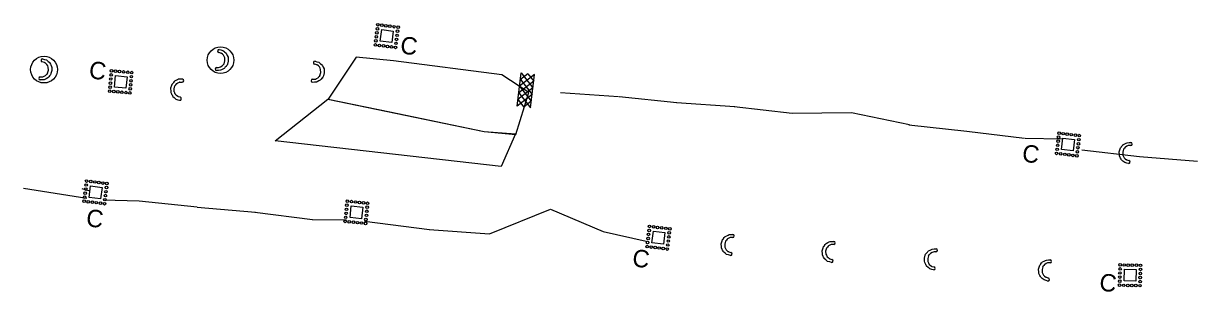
# Model space of a CAD drawing. Extents: x 2470000 to 2520000, y 340000 to 380000.
# Drawn here: x 2480859 to 2481867, y 366051 to 366283 of the extents above; entities that cross this region are included whole.
import ezdxf

# ---------------------------------------------------------------- set-up
doc = ezdxf.new("R2010")
doc.units = 0
for name, color, linetype in [('Bare Soil (Coastal) Drainage Area Border FG Drainage', 7, 'Continuous'), ('Coir Fiber Wattle with PAM Both CELL', 7, 'Continuous'), ('Coir Fiber Wattle with PAM CG CELL', 7, 'Continuous'), ('Label C CG CELL', 7, 'Continuous'), ('Prop Guardrail Anchor Unit CELL', 7, 'Continuous'), ('Prop Structure Anchor Unit CELL', 7, 'Continuous'), ('Rock Inlet Sediment Trap Type C CG CELL', 7, 'Continuous'), ('Rock Silt Check Type A Both CELL', 7, 'Continuous'), ('Scratch_Level_5', 7, 'Continuous'), ('Sheet Data Field CELL', 7, 'Continuous'), ('Wattle Both CELL', 7, 'Continuous'), ('Wattle CG CELL', 7, 'Continuous')]:
    doc.layers.add(name, color=color, linetype=linetype)

# ---------------------------------------------------------------- blocks, each defined once
blk = doc.blocks.new('C2')
at = {"layer": 'Prop Guardrail Anchor Unit CELL'}
blk.add_text('C', height=0.3, dxfattribs=at).set_placement((-0.161, -0.136))
blk = doc.blocks.new('C1')
at = {"layer": 'Label C CG CELL'}
blk.add_text('C', height=0.3, dxfattribs=at).set_placement((-0.161, -0.136))

msp = doc.modelspace()

# ---------------------------------------------------------------- linework, layer by layer
at = {"layer": 'Bare Soil (Coastal) Drainage Area Border FG Drainage'}
for points in [[(2481144.5, 366253.7), (2481120.5, 366217.8), (2481173.6, 366206.7), (2481254.6, 366189.8), (2481281.6, 366187.4), (2481292.9, 366223.5), (2481269.6, 366238.6), (2481176.7, 366250.7)], [(2481281.4, 366187.9), (2481269.1, 366159.6), (2481074.9, 366181.9), (2481120.2, 366217.8), (2481254.6, 366189.8)]]:
    msp.add_lwpolyline(points, close=True, dxfattribs=at)
at = {"layer": 'Coir Fiber Wattle with PAM Both CELL'}
for p, q in [((2481028.4, 366257.3), (2481026.6, 366257.9)), ((2481028.4, 366257.3), (2481028.7, 366257.2)), ((2481029.8, 366256.3), (2481028.7, 366257.2)), ((2481030.6, 366255.6), (2481029.8, 366256.3)), ((2481028.2, 366245.5), (2481029.5, 366246.2)), ((2481029.6, 366246.4), (2481029.5, 366246.2)), ((2481029.6, 366246.4), (2481030.3, 366247.2)), ((2481031.1, 366248.2), (2481030.3, 366247.2)), ((2481031.2, 366254.3), (2481030.6, 366255.6)), ((2481031.1, 366248.2), (2481031.8, 366250.7)), ((2481031.7, 366253.2), (2481031.2, 366254.3)), ((2481031.8, 366250.7), (2481031.7, 366253.2)), ((2481031.8, 366250.7), (2481031.8, 366250.7)), ((2481024.8, 366244.9), (2481026.4, 366245)), ((2481026.4, 366245), (2481027.2, 366245.1)), ((2481027.2, 366245.1), (2481028.2, 366245.5))]:
    msp.add_line(p, q, dxfattribs=at)
msp.add_lwpolyline([(2481026.9, 366260.5), (2481028.4, 366260), (2481030.1, 366259.5), (2481030.8, 366259), (2481031.6, 366258.3), (2481032.9, 366257.2), (2481033, 366257.1), (2481033.2, 366256.8), (2481033.2, 366256.7), (2481033.6, 366255.8), (2481033.9, 366255.2), (2481034.6, 366253.9), (2481034.6, 366252.9), (2481034.8, 366250.3), (2481034.8, 366250.3), (2481034, 366247.8), (2481033.7, 366246.8), (2481032.9, 366246), (2481032.8, 366245.8), (2481032.2, 366245.1), (2481031.7, 366244.5), (2481031.6, 366244.4), (2481031.3, 366244.1), (2481031.3, 366244.1), (2481030, 366243.4), (2481028.8, 366242.8), (2481028, 366242.5), (2481026.3, 366242.4), (2481024.7, 366242.3)], dxfattribs=at)
msp.add_circle((2481028.1, 366251.2), 11.5, dxfattribs=at)
for centre, radius, start in [((2481026.8, 366259.2), 1.3, 83.0023), ((2481024.9, 366243.6), 1.33, 91.8897)]:
    msp.add_arc(centre, radius, start, 263.0023, dxfattribs=at)
at = {"layer": 'Coir Fiber Wattle with PAM CG CELL'}
for p, q in [((2480876.8, 366249.2), (2480875, 366249.8)), ((2480876.8, 366249.2), (2480877.1, 366249.1)), ((2480878.3, 366248.2), (2480877.1, 366249.1)), ((2480879, 366247.5), (2480878.3, 366248.2)), ((2480879.7, 366246.2), (2480879, 366247.5)), ((2480880.2, 366245.1), (2480879.7, 366246.2)), ((2480873.3, 366236.8), (2480874.8, 366236.9)), ((2480874.8, 366236.9), (2480875.6, 366237)), ((2480875.6, 366237), (2480876.6, 366237.4)), ((2480876.6, 366237.4), (2480877.9, 366238.1)), ((2480878.1, 366238.3), (2480877.9, 366238.1)), ((2480878.1, 366238.3), (2480878.8, 366239.1)), ((2480879.5, 366240.1), (2480878.8, 366239.1)), ((2480879.5, 366240.1), (2480880.3, 366242.6)), ((2480880.3, 366242.6), (2480880.2, 366245.1)), ((2480880.3, 366242.6), (2480880.3, 366242.6))]:
    msp.add_line(p, q, dxfattribs=at)
msp.add_lwpolyline([(2480875.3, 366252.4), (2480876.8, 366251.9), (2480878.6, 366251.4), (2480879.2, 366250.9), (2480880, 366250.2), (2480881.4, 366249.1), (2480881.4, 366249.1), (2480881.6, 366248.7), (2480881.6, 366248.6), (2480882, 366247.7), (2480882.3, 366247.1), (2480883, 366245.8), (2480883.1, 366244.8), (2480883.2, 366242.2), (2480883.2, 366242.2), (2480882.4, 366239.7), (2480882.1, 366238.7), (2480881.4, 366237.9), (2480881.2, 366237.7), (2480880.6, 366237), (2480880.1, 366236.4), (2480880, 366236.3), (2480879.8, 366236), (2480879.8, 366236), (2480878.4, 366235.3), (2480877.2, 366234.7), (2480876.5, 366234.4), (2480874.7, 366234.3), (2480873.2, 366234.2)], dxfattribs=at)
msp.add_circle((2480876.5, 366243.1), 11.5, dxfattribs=at)
for centre, radius, start in [((2480875.2, 366251.1), 1.3, 83.0023), ((2480873.3, 366235.5), 1.33, 91.8897)]:
    msp.add_arc(centre, radius, start, 263.0023, dxfattribs=at)
at = {"layer": 'Prop Structure Anchor Unit CELL'}
for points in [[(2481166.5, 366277.5), (2481176.4, 366276.3), (2481175.2, 366266.4), (2481165.2, 366267.6)], [(2481751.6, 366184.2), (2481761.6, 366183), (2481760.3, 366173.1), (2481750.4, 366174.3)], [(2480916.4, 366143), (2480926.3, 366141.8), (2480925.1, 366131.9), (2480915.2, 366133.1)], [(2481140.4, 366125.8), (2481150.3, 366124.8), (2481149.3, 366114.8), (2481139.4, 366115.8)], [(2481399.9, 366104), (2481409.8, 366102.8), (2481408.6, 366092.9), (2481398.6, 366094.1)], [(2481804.2, 366061.3), (2481804.4, 366071.3), (2481814.4, 366071), (2481814.2, 366061)]]:
    msp.add_lwpolyline(points, close=True, dxfattribs=at)
for centre in [(2481162.8, 366278.2), (2481163.2, 366281.7), (2481166.7, 366281.3), (2481170.1, 366280.8), (2481173.6, 366280.4), (2481177.1, 366280), (2481180.1, 366276.1), (2481180.6, 366279.6), (2481161.5, 366267.8), (2481161.9, 366271.3), (2481162.3, 366274.7), (2481178.8, 366265.7), (2481179.3, 366269.1), (2481179.7, 366272.6), (2481161.1, 366264.3), (2481164.5, 366263.9), (2481168, 366263.5), (2481171.5, 366263), (2481174.9, 366262.6), (2481178.4, 366262.2), (2481747.9, 366184.9), (2481748.4, 366188.4), (2481751.8, 366188), (2481755.3, 366187.6), (2481758.8, 366187.1), (2481762.3, 366186.7), (2481765.7, 366186.3), (2481746.7, 366174.5), (2481747.1, 366178), (2481747.5, 366181.5), (2481764.5, 366175.9), (2481764.9, 366179.3), (2481765.3, 366182.8), (2481746.2, 366171), (2481749.7, 366170.6), (2481753.2, 366170.2), (2481756.7, 366169.8), (2481760.1, 366169.3), (2481763.6, 366168.9), (2481764, 366172.4), (2480913.1, 366147.2), (2480916.6, 366146.8), (2480920.1, 366146.4), (2480923.6, 366146), (2480927, 366145.5), (2480930.5, 366145.1), (2480911.9, 366136.8), (2480912.3, 366140.3), (2480912.7, 366143.8), (2480929.2, 366134.7), (2480929.7, 366138.1), (2480930.1, 366141.6), (2480911, 366129.9), (2480911.4, 366133.3), (2480914.5, 366129.4), (2480918, 366129), (2480921.4, 366128.6), (2480924.9, 366128.2), (2480928.4, 366127.7), (2480928.8, 366131.2), (2481136.6, 366126.4), (2481137, 366129.9), (2481140.5, 366129.5), (2481144, 366129.2), (2481147.4, 366128.8), (2481150.9, 366128.5), (2481154.1, 366124.7), (2481154.4, 366128.1), (2481135.6, 366116), (2481135.9, 366119.4), (2481136.3, 366122.9), (2481153, 366114.2), (2481153.4, 366117.7), (2481153.7, 366121.2), (2481135.2, 366112.5), (2481138.7, 366112.1), (2481142.2, 366111.8), (2481145.7, 366111.4), (2481149.2, 366111.1), (2481152.7, 366110.7), (2481396.2, 366104.7), (2481396.6, 366108.2), (2481400.1, 366107.8), (2481403.5, 366107.3), (2481407, 366106.9), (2481410.5, 366106.5), (2481414, 366106.1), (2481394.9, 366094.3), (2481395.3, 366097.8), (2481395.7, 366101.3), (2481412.7, 366095.6), (2481413.1, 366099.1), (2481413.5, 366102.6), (2481394.5, 366090.8), (2481397.9, 366090.4), (2481401.4, 366090), (2481404.9, 366089.6), (2481408.3, 366089.1), (2481411.8, 366088.7), (2481412.2, 366092.2), (2481800.8, 366075.1), (2481804.3, 366075), (2481807.7, 366074.9), (2481811.2, 366074.9), (2481814.7, 366074.8), (2481818.2, 366074.7), (2481800.5, 366064.6), (2481800.7, 366071.6), (2481800.6, 366068.1), (2481818, 366064.2), (2481818.2, 366071.2), (2481818.1, 366067.7), (2481800.3, 366057.6), (2481800.4, 366061.1), (2481803.8, 366057.5), (2481807.3, 366057.4), (2481810.8, 366057.4), (2481814.3, 366057.3), (2481817.8, 366057.2), (2481817.9, 366060.7)]:
    msp.add_circle(centre, 1.12, dxfattribs=at)
at = {"layer": 'Rock Inlet Sediment Trap Type C CG CELL'}
msp.add_lwpolyline([(2480937.8, 366237.9), (2480947.8, 366237), (2480946.9, 366227.1), (2480937, 366227.9)], close=True, dxfattribs=at)
for centre in [(2480933.8, 366235), (2480934.1, 366238.5), (2480934.4, 366242), (2480937.9, 366241.7), (2480941.4, 366241.4), (2480944.9, 366241.1), (2480948.4, 366240.8), (2480951.5, 366237), (2480951.8, 366240.5), (2480933.2, 366228), (2480933.5, 366231.5), (2480950.6, 366226.5), (2480950.9, 366230), (2480951.2, 366233.5), (2480932.9, 366224.5), (2480936.4, 366224.2), (2480939.9, 366223.9), (2480943.4, 366223.6), (2480946.9, 366223.3), (2480950.3, 366223)]:
    msp.add_circle(centre, 1.12, dxfattribs=at)
at = {"layer": 'Rock Silt Check Type A Both CELL'}
for p, q in [((2481282.8, 366211.6), (2481286.3, 366240.3)), ((2481297.8, 366238.9), (2481284.9, 366228.8)), ((2481292, 366239.6), (2481285.6, 366234.5)), ((2481286.3, 366240.3), (2481296.4, 366227.4)), ((2481292, 366239.6), (2481297.1, 366233.1)), ((2481294.3, 366210.2), (2481297.8, 366238.9)), ((2481296.4, 366227.4), (2481283.5, 366217.3)), ((2481297.1, 366233.1), (2481284.2, 366223.1)), ((2481284.9, 366228.8), (2481295, 366215.9)), ((2481285.6, 366234.5), (2481295.7, 366221.7)), ((2481295.7, 366221.7), (2481282.8, 366211.6)), ((2481283.6, 366217.2), (2481288.5, 366210.9)), ((2481284.2, 366223.1), (2481294.3, 366210.2)), ((2481295, 366215.9), (2481288.5, 366210.9))]:
    msp.add_line(p, q, dxfattribs=at)
at = {"layer": 'Sheet Data Field CELL'}
for p, q in [((2481370, 366219.7), (2481320.1, 366223)), ((2481420.1, 366214.6), (2481370.4, 366219.6)), ((2481469.7, 366211.2), (2481419.8, 366214.6)), ((2481519.2, 366205.3), (2481469.2, 366211.2)), ((2481570.1, 366205.8), (2481519.2, 366205.3)), ((2481619.8, 366195.5), (2481570.1, 366205.8)), ((2481619.3, 366195.5), (2481669, 366190)), ((2481669, 366190), (2481718.7, 366184)), ((2481719.1, 366184), (2481751.1, 366183.5)), ((2481767.9, 366174.1), (2481817.5, 366168.2)), ((2481817.4, 366168.2), (2481867.2, 366164.2)), ((2480858.9, 366141.2), (2480913.3, 366132.4)), ((2480927.3, 366131.1), (2480958.2, 366130.3)), ((2480958.2, 366130.3), (2481007.9, 366124.9)), ((2481008.1, 366124.8), (2481058, 366120.5)), ((2481057.5, 366120.5), (2481107.1, 366114)), ((2481259.2, 366101.8), (2481311.4, 366123.1)), ((2481311.4, 366123.1), (2481356.7, 366103.8)), ((2481107.3, 366113.9), (2481136.1, 366114.1)), ((2481151.7, 366112.8), (2481207.5, 366105.6)), ((2481207.4, 366105.6), (2481259.2, 366101.8)), ((2481356.7, 366103.8), (2481393.8, 366095.6))]:
    msp.add_line(p, q, dxfattribs=at)
msp.add_lwpolyline([(2480909.1, 366140.9), (2480915.9, 366138.7)], dxfattribs=at)
at = {"layer": 'Wattle Both CELL'}
for p, q in [((2481110.8, 366247.2), (2481109, 366247.8)), ((2481110.8, 366247.2), (2481111.1, 366247.1)), ((2481112.2, 366246.2), (2481111.1, 366247.1)), ((2481113, 366245.5), (2481112.2, 366246.2)), ((2481110.6, 366235.4), (2481111.9, 366236.1)), ((2481112, 366236.2), (2481111.9, 366236.1)), ((2481112, 366236.2), (2481112.7, 366237.1)), ((2481113.5, 366238), (2481112.7, 366237.1)), ((2481113.6, 366244.2), (2481113, 366245.5)), ((2481113.5, 366238), (2481114.2, 366240.6)), ((2481114.1, 366243.1), (2481113.6, 366244.2)), ((2481114.2, 366240.6), (2481114.1, 366243.1)), ((2481114.2, 366240.6), (2481114.2, 366240.6)), ((2481107.2, 366234.8), (2481108.8, 366234.9)), ((2481108.8, 366234.9), (2481109.6, 366234.9)), ((2481109.6, 366234.9), (2481110.6, 366235.4)), ((2481803.7, 366174.5), (2481804.5, 366175.5)), ((2481805.2, 366176.3), (2481804.5, 366175.5)), ((2481805.2, 366176.3), (2481805.3, 366176.5)), ((2481806.6, 366177.2), (2481805.3, 366176.5)), ((2481807.6, 366177.7), (2481806.6, 366177.2)), ((2481808.4, 366177.7), (2481807.6, 366177.7)), ((2481809.9, 366177.8), (2481808.4, 366177.7)), ((2481803.7, 366174.5), (2481803, 366172)), ((2481803, 366172), (2481803, 366172)), ((2481803, 366172), (2481803.1, 366169.5)), ((2481803.1, 366169.5), (2481803.6, 366168.4)), ((2481803.6, 366168.4), (2481804.2, 366167.1)), ((2481804.2, 366167.1), (2481805, 366166.4)), ((2481805, 366166.4), (2481806.1, 366165.5)), ((2481806.4, 366165.4), (2481806.1, 366165.5)), ((2481806.4, 366165.4), (2481808.2, 366164.8)), ((2481461.9, 366095.4), (2481461.1, 366092.9)), ((2481461.9, 366095.4), (2481462.6, 366096.3)), ((2481463.3, 366097.2), (2481462.6, 366096.3)), ((2481463.3, 366097.2), (2481463.5, 366097.4)), ((2481464.8, 366098), (2481463.5, 366097.4)), ((2481465.7, 366098.5), (2481464.8, 366098)), ((2481466.5, 366098.6), (2481465.7, 366098.5)), ((2481468.1, 366098.7), (2481466.5, 366098.6)), ((2481461.1, 366092.9), (2481461.1, 366092.9)), ((2481461.1, 366092.9), (2481461.2, 366090.4)), ((2481461.2, 366090.4), (2481461.7, 366089.3)), ((2481461.7, 366089.3), (2481462.3, 366088)), ((2481462.3, 366088), (2481463.1, 366087.3)), ((2481463.1, 366087.3), (2481464.2, 366086.3)), ((2481464.6, 366086.2), (2481464.2, 366086.3)), ((2481464.6, 366086.2), (2481466.3, 366085.7)), ((2481548.6, 366089.4), (2481547.8, 366086.9)), ((2481547.8, 366086.9), (2481547.8, 366086.9)), ((2481547.8, 366086.9), (2481548, 366084.4)), ((2481548.6, 366089.4), (2481549.4, 366090.4)), ((2481550.1, 366091.2), (2481549.4, 366090.4)), ((2481550.1, 366091.2), (2481550.2, 366091.4)), ((2481551.5, 366092.1), (2481550.2, 366091.4)), ((2481552.5, 366092.6), (2481551.5, 366092.1)), ((2481553.3, 366092.6), (2481552.5, 366092.6)), ((2481554.8, 366092.7), (2481553.3, 366092.6)), ((2481637.8, 366084.8), (2481637.1, 366083.9)), ((2481637.8, 366084.8), (2481637.9, 366085)), ((2481639.2, 366085.6), (2481637.9, 366085)), ((2481640.2, 366086.1), (2481639.2, 366085.6)), ((2481641, 366086.2), (2481640.2, 366086.1)), ((2481642.6, 366086.2), (2481641, 366086.2)), ((2481548, 366084.4), (2481548.5, 366083.3)), ((2481548.5, 366083.3), (2481549.1, 366082)), ((2481549.1, 366082), (2481549.9, 366081.3)), ((2481549.9, 366081.3), (2481551, 366080.4)), ((2481551.3, 366080.3), (2481551, 366080.4)), ((2481551.3, 366080.3), (2481553.1, 366079.7)), ((2481636.3, 366083), (2481635.6, 366080.5)), ((2481635.6, 366080.5), (2481635.6, 366080.5)), ((2481635.6, 366080.5), (2481635.7, 366077.9)), ((2481635.7, 366077.9), (2481636.2, 366076.8)), ((2481636.2, 366076.8), (2481636.8, 366075.5)), ((2481636.3, 366083), (2481637.1, 366083.9)), ((2481636.8, 366075.5), (2481637.6, 366074.9)), ((2481637.6, 366074.9), (2481638.7, 366073.9)), ((2481735.9, 366075.3), (2481735.2, 366074.5)), ((2481735.9, 366075.3), (2481736, 366075.5)), ((2481737.3, 366076.2), (2481736, 366075.5)), ((2481738.3, 366076.7), (2481737.3, 366076.2)), ((2481739.1, 366076.7), (2481738.3, 366076.7)), ((2481740.7, 366076.8), (2481739.1, 366076.7)), ((2481639, 366073.8), (2481638.7, 366073.9)), ((2481639, 366073.8), (2481640.8, 366073.3)), ((2481734.4, 366073.5), (2481733.7, 366071)), ((2481733.7, 366071), (2481733.7, 366071)), ((2481733.7, 366071), (2481733.8, 366068.5)), ((2481733.8, 366068.5), (2481734.3, 366067.4)), ((2481734.3, 366067.4), (2481734.9, 366066.1)), ((2481734.4, 366073.5), (2481735.2, 366074.5)), ((2481734.9, 366066.1), (2481735.7, 366065.4)), ((2481735.7, 366065.4), (2481736.8, 366064.5)), ((2481737.1, 366064.4), (2481736.8, 366064.5)), ((2481737.1, 366064.4), (2481738.9, 366063.8))]:
    msp.add_line(p, q, dxfattribs=at)
for points in [[(2481109.3, 366250.4), (2481110.8, 366249.9), (2481112.5, 366249.4), (2481113.2, 366248.8), (2481114, 366248.2), (2481115.3, 366247.1), (2481115.4, 366247), (2481115.6, 366246.6), (2481115.6, 366246.6), (2481116, 366245.7), (2481116.3, 366245.1), (2481117, 366243.8), (2481117, 366242.7), (2481117.2, 366240.2), (2481117.2, 366240.2), (2481116.4, 366237.7), (2481116.1, 366236.7), (2481115.3, 366235.8), (2481115.2, 366235.7), (2481114.5, 366234.9), (2481114.1, 366234.4), (2481114, 366234.2), (2481113.7, 366234), (2481113.7, 366234), (2481112.4, 366233.3), (2481111.1, 366232.7), (2481110.4, 366232.4), (2481108.7, 366232.2), (2481107.1, 366232.1)], [(2481807.9, 366162.2), (2481806.4, 366162.7), (2481804.7, 366163.2), (2481804, 366163.7), (2481803.2, 366164.4), (2481801.8, 366165.5), (2481801.8, 366165.6), (2481801.6, 366166), (2481801.6, 366166), (2481801.2, 366166.9), (2481800.9, 366167.5), (2481800.2, 366168.8), (2481800.2, 366169.8), (2481800, 366172.4), (2481800, 366172.4), (2481800.8, 366174.9), (2481801.1, 366175.9), (2481801.9, 366176.7), (2481802, 366176.9), (2481802.6, 366177.6), (2481803.1, 366178.2), (2481803.2, 366178.3), (2481803.5, 366178.6), (2481803.5, 366178.6), (2481804.8, 366179.3), (2481806, 366179.9), (2481806.8, 366180.2), (2481808.5, 366180.3), (2481810.1, 366180.4)], [(2481466, 366083.1), (2481464.5, 366083.6), (2481462.8, 366084.1), (2481462.1, 366084.6), (2481461.4, 366085.3), (2481460, 366086.4), (2481460, 366086.4), (2481459.8, 366086.8), (2481459.7, 366086.9), (2481459.3, 366087.8), (2481459, 366088.4), (2481458.4, 366089.7), (2481458.3, 366090.7), (2481458.1, 366093.3), (2481458.1, 366093.3), (2481458.9, 366095.8), (2481459.3, 366096.8), (2481460, 366097.6), (2481460.2, 366097.8), (2481460.8, 366098.5), (2481461.3, 366099.1), (2481461.4, 366099.2), (2481461.6, 366099.5), (2481461.6, 366099.5), (2481463, 366100.2), (2481464.2, 366100.7), (2481464.9, 366101.1), (2481466.7, 366101.2), (2481468.2, 366101.3)], [(2481552.8, 366077.1), (2481551.3, 366077.6), (2481549.5, 366078.1), (2481548.9, 366078.6), (2481548.1, 366079.3), (2481546.7, 366080.4), (2481546.7, 366080.5), (2481546.5, 366080.9), (2481546.5, 366080.9), (2481546.1, 366081.8), (2481545.8, 366082.4), (2481545.1, 366083.7), (2481545.1, 366084.7), (2481544.9, 366087.3), (2481544.9, 366087.3), (2481545.7, 366089.8), (2481546, 366090.8), (2481546.8, 366091.6), (2481546.9, 366091.8), (2481547.5, 366092.6), (2481548, 366093.1), (2481548.1, 366093.2), (2481548.4, 366093.5), (2481548.4, 366093.5), (2481549.7, 366094.2), (2481550.9, 366094.8), (2481551.7, 366095.1), (2481553.4, 366095.2), (2481555, 366095.3)], [(2481640.5, 366070.7), (2481639, 366071.1), (2481637.3, 366071.7), (2481636.6, 366072.2), (2481635.9, 366072.8), (2481634.5, 366074), (2481634.4, 366074), (2481634.3, 366074.4), (2481634.2, 366074.5), (2481633.8, 366075.3), (2481633.5, 366075.9), (2481632.9, 366077.2), (2481632.8, 366078.3), (2481632.6, 366080.8), (2481632.6, 366080.8), (2481633.4, 366083.4), (2481633.7, 366084.3), (2481634.5, 366085.2), (2481634.6, 366085.4), (2481635.3, 366086.1), (2481635.7, 366086.7), (2481635.8, 366086.8), (2481636.1, 366087.1), (2481636.1, 366087.1), (2481637.5, 366087.7), (2481638.7, 366088.3), (2481639.4, 366088.7), (2481641.1, 366088.8), (2481642.7, 366088.9)], [(2481738.6, 366061.2), (2481737.1, 366061.7), (2481735.4, 366062.2), (2481734.7, 366062.7), (2481733.9, 366063.4), (2481732.6, 366064.5), (2481732.5, 366064.6), (2481732.3, 366065), (2481732.3, 366065), (2481731.9, 366065.9), (2481731.6, 366066.5), (2481730.9, 366067.8), (2481730.9, 366068.8), (2481730.7, 366071.4), (2481730.7, 366071.4), (2481731.5, 366073.9), (2481731.8, 366074.9), (2481732.6, 366075.7), (2481732.7, 366075.9), (2481733.3, 366076.7), (2481733.8, 366077.2), (2481733.9, 366077.3), (2481734.2, 366077.6), (2481734.2, 366077.6), (2481735.5, 366078.3), (2481736.7, 366078.9), (2481737.5, 366079.2), (2481739.2, 366079.3), (2481740.8, 366079.5)]]:
    msp.add_lwpolyline(points, dxfattribs=at)
for centre, radius, start, end in [((2481109.1, 366249.1), 1.3, 83.0023, 263.0023), ((2481107.3, 366233.5), 1.33, 91.8897, 263.0023), ((2481809.9, 366179.1), 1.33, 271.8897, 83.0023), ((2481808, 366163.5), 1.3, 263.0023, 83.0023), ((2481468, 366100), 1.33, 271.8897, 83.0023), ((2481554.8, 366094), 1.33, 271.8897, 83.0023), ((2481466.2, 366084.4), 1.3, 263.0023, 83.0023), ((2481642.5, 366087.6), 1.33, 271.8897, 83.0023), ((2481552.9, 366078.4), 1.3, 263.0023, 83.0023), ((2481740.6, 366078.1), 1.33, 271.8897, 83.0023), ((2481640.7, 366072), 1.3, 263.0023, 83.0023), ((2481738.7, 366062.5), 1.3, 263.0023, 83.0023)]:
    msp.add_arc(centre, radius, start, end, dxfattribs=at)
at = {"layer": 'Wattle CG CELL'}
for p, q in [((2480988.2, 366226.6), (2480988.9, 366229.1)), ((2480988.2, 366226.6), (2480988.2, 366226.6)), ((2480988.3, 366224), (2480988.2, 366226.6)), ((2480988.9, 366229.1), (2480989.7, 366230)), ((2480989.7, 366230), (2480990.6, 366231.1)), ((2480990.6, 366231.1), (2480991.5, 366231.6)), ((2480991.5, 366231.6), (2480992.8, 366232.2)), ((2480993.2, 366232.2), (2480992.8, 366232.2)), ((2480993.2, 366232.2), (2480995, 366232.3)), ((2480988.3, 366224), (2480988.8, 366222.9)), ((2480989.2, 366221.9), (2480988.8, 366222.9)), ((2480989.2, 366221.9), (2480989.3, 366221.7)), ((2480990.4, 366220.7), (2480989.3, 366221.7)), ((2480991.3, 366220), (2480990.4, 366220.7)), ((2480992, 366219.8), (2480991.3, 366220)), ((2480993.5, 366219.3), (2480992, 366219.8))]:
    msp.add_line(p, q, dxfattribs=at)
msp.add_lwpolyline([(2480995.4, 366234.9), (2480993.8, 366234.8), (2480992, 366234.8), (2480991.2, 366234.4), (2480990.3, 366234), (2480988.7, 366233.2), (2480988.7, 366233.2), (2480988.4, 366232.8), (2480988.3, 366232.8), (2480987.7, 366232.1), (2480987.3, 366231.5), (2480986.3, 366230.4), (2480986, 366229.4), (2480985.2, 366227), (2480985.2, 366227), (2480985.4, 366224.4), (2480985.4, 366223.3), (2480985.9, 366222.3), (2480986, 366222.1), (2480986.5, 366221.3), (2480986.8, 366220.6), (2480986.9, 366220.4), (2480987, 366220.1), (2480987, 366220.1), (2480988.2, 366219.1), (2480989.2, 366218.3), (2480989.8, 366217.8), (2480991.5, 366217.2), (2480993, 366216.7)], dxfattribs=at)
for centre, radius, end in [((2480995.2, 366233.6), 1.3, 82.7437), ((2480993.1, 366218), 1.33, 73.8563)]:
    msp.add_arc(centre, radius, 262.7437, end, dxfattribs=at)

# ---------------------------------------------------------------- block references
at = {"layer": 'Prop Guardrail Anchor Unit CELL', "xscale": 50, "yscale": 50, "rotation": -6.997703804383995}
msp.add_blockref('C2', (2481390, 366079.7), dxfattribs=at)
at = {"layer": 'Prop Structure Anchor Unit CELL'}
for p, xscale, yscale, rotation in [((2481190.7, 366262.8), 49.99999999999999, 50.00000000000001, -6.997703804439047), ((2480920.9, 366114.2), 50.00000000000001, 49.99999999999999, -6.997703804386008), ((2481791.1, 366058.9), 50.00000000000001, 49.99999999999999, -6.997703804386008)]:
    msp.add_blockref('C2', p, dxfattribs=dict(at, xscale=xscale, yscale=yscale, rotation=rotation))
at = {"layer": 'Rock Inlet Sediment Trap Type C CG CELL', "xscale": 49.99999999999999, "yscale": 50.00000000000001, "rotation": -6.997703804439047}
msp.add_blockref('C1', (2480923.3, 366241.5), dxfattribs=at)
at = {"layer": 'Scratch_Level_5', "xscale": 50.00000000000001, "yscale": 49.99999999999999, "rotation": -6.997703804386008}
msp.add_blockref('C2', (2481724.8, 366169.8), dxfattribs=at)

doc.saveas('drawing.dxf')
